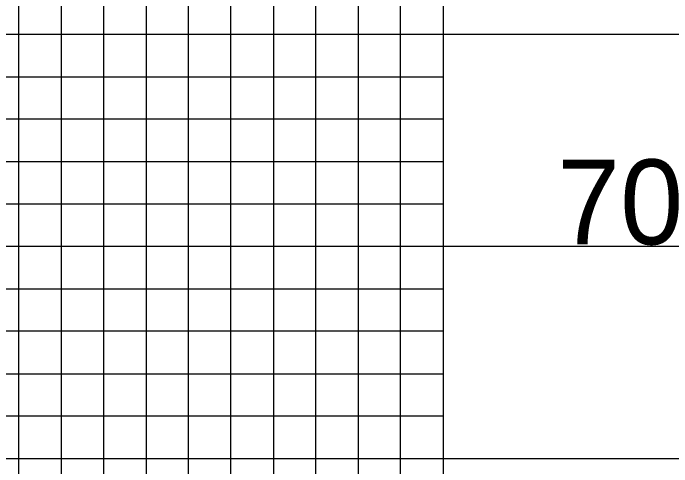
# Model space of a CAD drawing. Extents: x 1524869 to 1526553, y 501099 to 502199.
# Drawn here: x 1526435.4 to 1526513, y 501222.6 to 501276.1 of the extents above; entities that cross this region are included whole.
import ezdxf

# ---------------------------------------------------------------- set-up
doc = ezdxf.new("R2010")
doc.units = 0
for name, color, linetype in [('Exist Vertical Profile Vertical Axis Label', 7, 'Continuous'), ('Sheet Layout Profile Border Port 2', 7, 'Continuous'), ('Sheet Profile Grid Major CELL', 7, 'Continuous'), ('Sheet Profile Grid Middle CELL', 7, 'Continuous'), ('Sheet Profile Grid Minor CELL', 7, 'Continuous')]:
    doc.layers.add(name, color=color, linetype=linetype)

msp = doc.modelspace()

# ---------------------------------------------------------------- linework, layer by layer
at = {"layer": 'Sheet Layout Profile Border Port 2'}
msp.add_lwpolyline([(1525086.08, 501648.562), (1526486.08, 501648.562), (1526486.08, 501148.562), (1525086.08, 501148.562)], close=True, dxfattribs=at)
at = {"layer": 'Sheet Profile Grid Major CELL'}
for points in [[(1525986.08, 501148.562), (1526036.08, 501148.562), (1526036.08, 501648.562), (1526086.08, 501648.562), (1526086.08, 501148.562), (1526136.08, 501148.562), (1526136.08, 501648.562), (1526186.08, 501648.562), (1526186.08, 501148.562), (1526236.08, 501148.562), (1526236.08, 501648.562), (1526286.08, 501648.562), (1526286.08, 501148.562), (1526336.08, 501148.562), (1526336.08, 501648.562), (1526386.08, 501648.562), (1526386.08, 501148.562), (1526436.08, 501148.562), (1526436.08, 501148.562), (1526436.08, 501648.562), (1526486.08, 501648.562), (1526486.08, 501148.562)], [(1526536.08, 501248.562), (1525036.08, 501248.562), (1525036.08, 501248.562), (1525036.08, 501198.562), (1526536.08, 501198.562)]]:
    msp.add_lwpolyline(points, dxfattribs=at)
at = {"layer": 'Sheet Profile Grid Middle CELL'}
for points in [[(1526011.08, 501148.562), (1526061.08, 501148.562), (1526061.08, 501648.562), (1526111.08, 501648.562), (1526111.08, 501148.562), (1526161.08, 501148.562), (1526161.08, 501648.562), (1526211.08, 501648.562), (1526211.08, 501148.562), (1526261.08, 501148.562), (1526261.08, 501648.562), (1526311.08, 501648.562), (1526311.08, 501148.562), (1526361.08, 501148.562), (1526361.08, 501648.562), (1526411.08, 501648.562), (1526411.08, 501148.562), (1526461.08, 501148.562), (1526461.08, 501648.562)], [(1526536.08, 501273.562), (1525036.08, 501273.562), (1525036.08, 501223.562), (1526536.08, 501223.562)]]:
    msp.add_lwpolyline(points, dxfattribs=at)
at = {"layer": 'Sheet Profile Grid Minor CELL'}
for p, q in [((1525086.08, 501268.562), (1526486.08, 501268.562)), ((1526486.08, 501263.562), (1525086.08, 501263.562)), ((1525086.08, 501258.562), (1526486.08, 501258.562)), ((1526486.08, 501253.562), (1525086.08, 501253.562)), ((1525086.08, 501243.562), (1526486.08, 501243.562)), ((1526486.08, 501238.562), (1525086.08, 501238.562)), ((1525086.08, 501233.562), (1526486.08, 501233.562)), ((1526486.08, 501228.562), (1525086.08, 501228.562))]:
    msp.add_line(p, q, dxfattribs=at)
for points in [[(1526441.08, 501648.562), (1526441.08, 501148.562), (1526446.08, 501148.562), (1526446.08, 501648.562)], [(1526451.08, 501648.562), (1526451.08, 501148.562), (1526456.08, 501148.562), (1526456.08, 501648.562)], [(1526466.08, 501648.562), (1526466.08, 501148.562), (1526471.08, 501148.562), (1526471.08, 501648.562)], [(1526476.08, 501648.562), (1526476.08, 501148.562), (1526481.08, 501148.562), (1526481.08, 501648.562)]]:
    msp.add_lwpolyline(points, dxfattribs=at)

# ---------------------------------------------------------------- texts
at = {"layer": 'Exist Vertical Profile Vertical Axis Label'}
msp.add_text('700', height=10, dxfattribs=at).set_placement((1526499.512, 501248.812))

doc.saveas('drawing.dxf')
